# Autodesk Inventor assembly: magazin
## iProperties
Created: 2006-04
Part Number: magazin
Checked By: Проверил
Description: Наименование
Document SubType Name: Assembly
Mfg Approved By: Утвердил
Designer: Калинин
Engineer: Технолог
Manufacturer: Standard
Standards Organization: Custom
Author: Калинин
